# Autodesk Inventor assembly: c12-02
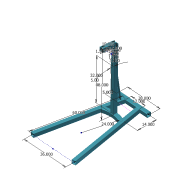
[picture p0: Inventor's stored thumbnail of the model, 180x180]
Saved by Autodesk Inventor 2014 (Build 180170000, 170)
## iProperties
Created: 2011-01
Part Number: c12-02
Document SubType Name: Assembly
Designer: Thom Tremblay
_SolveAssemblyDoc: Frame Generator Solve Assembly
_Version: 15.0.0
Author: Thom Tremblay
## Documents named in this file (3)
- C:\Inventor 2014 Essentials\Assemblies\Chapter 12\c12-02.iam
- C:\Inventor 2014 Essentials\Assemblies\Chapter 12\Frame\Frame c12-02.iam
- C:\Inventor 2014 Essentials\Parts\Chapter 12\c12-02.ipt
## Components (2 placed, 2 different names)
1. c12-02:1
2. Frame c12-02:1 [sub-assembly]
